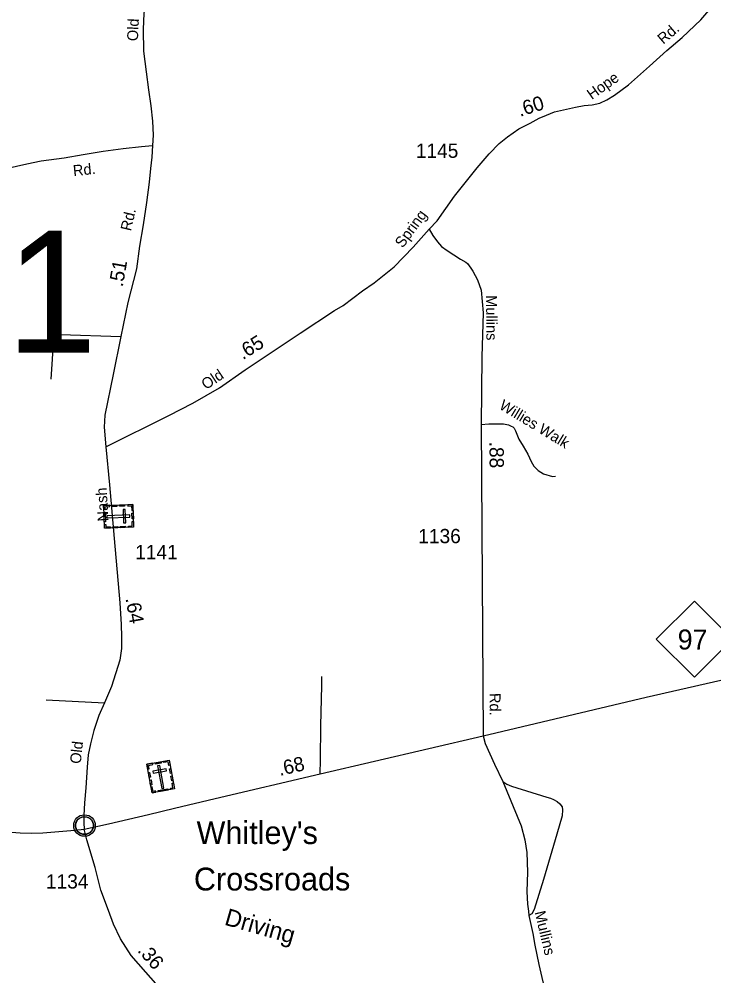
# Model space of a CAD drawing. Extents: x 2220236 to 2384410, y 720751 to 894131.
# Drawn here: x 2249679 to 2255753, y 766439 to 774813 of the extents above; entities that cross this region are included whole.
import ezdxf

# ---------------------------------------------------------------- set-up
doc = ezdxf.new("R2010")
doc.units = 0
doc.layers.add('Default', color=7, linetype='Continuous')

msp = doc.modelspace()

# ---------------------------------------------------------------- linework, layer by layer
at = {"layer": 'Default'}
msp.add_line((2249914.9, 768855.1), (2250426.3, 768828.7), dxfattribs=at)
for points in [[(2252290.3, 777623.5), (2252187.8, 777438.5), (2252085.3, 777242.3), (2251849.1, 776795.2), (2251710.9, 776529.9), (2251448, 776033.8), (2251392.3, 775951.3), (2251316.6, 775855.4), (2251158.3, 775661.4), (2251053.6, 775541), (2250986.8, 775447.4), (2250899.1, 775299.6), (2250856.5, 775184.3), (2250788.5, 774959.1), (2250769.2, 774863.9), (2250761.7, 774722.8), (2250766.2, 774531), (2250788.5, 774352.6), (2250808.5, 774194.3), (2250830.8, 774053.9), (2250844.2, 773920.1), (2250850.9, 773797.5), (2250845.5, 773705.6)], [(2253265, 772975.5), (2253333.2, 773046.7), (2253484, 773264.4), (2253684.2, 773511.1), (2253787.2, 773633), (2253875.7, 773724.5), (2253949.7, 773781.1), (2254046.8, 773853.7), (2254148.4, 773903), (2254225.3, 773945.1), (2254290.5, 773971.2), (2254359.1, 774001.2), (2254542.7, 774042.6), (2254618.4, 774055.4), (2254688, 774062.7), (2254757.6, 774078.6), (2254818.5, 774106.2), (2254885.3, 774146.9), (2255007.1, 774238.3), (2255189.9, 774402.3), (2255342.2, 774538.8), (2255475.9, 774650.5), (2255640.3, 774805.1), (2255710.7, 774887.4)], [(2247300.4, 773456), (2247377.2, 773386.3), (2247502, 773297.8), (2247596.3, 773248.4), (2247713.8, 773210.7), (2247824, 773184.5), (2247986.7, 773173.6), (2248156.7, 773167), (2248298.3, 773171.5), (2248369.4, 773175.8), (2248508.7, 773202), (2248595.7, 773226.6), (2248935.1, 773373.2), (2249150.2, 773418.9), (2249332.6, 773460.3), (2249566.1, 773503.9), (2249744.5, 773546), (2249870.7, 773573.5), (2250072.3, 773599.7), (2250239.2, 773628.7), (2250414.7, 773656.3), (2250588.7, 773679.5), (2250749.3, 773697.9), (2250845.5, 773705.6)], [(2250845.5, 773705.6), (2250839.7, 773605.5), (2250828.1, 773503.9), (2250815, 773386.3), (2250791.8, 773206.3), (2250762.8, 773013.3), (2250732.3, 772824.6), (2250704.1, 772625.9), (2250629.4, 772332.5), (2250567, 772035), (2250501.7, 771701.1), (2250429.2, 771347), (2250421.9, 771241), (2250437.9, 771068.3)], [(2250437.9, 771068.3), (2250987.7, 771344.1), (2251198, 771451.5), (2251430.1, 771586.5), (2251656.4, 771741.8), (2252136.5, 772064), (2252435.3, 772261.4), (2252510.7, 772306.4), (2252681.9, 772435.6), (2252782, 772505.3), (2252957.5, 772644.6), (2253124.3, 772815.9), (2253265, 772975.5)], [(2253265, 772975.5), (2253295.5, 772917.5), (2253336.1, 772863.8), (2253372.3, 772821.7), (2253421.7, 772788.3), (2253537.9, 772713), (2253584.1, 772685.5), (2253598.2, 772673.6), (2253628.6, 772633.8), (2253646.8, 772606), (2253687.1, 772529.9), (2253719, 772439.9), (2253736.4, 772241.1), (2253723.4, 771856.5), (2253717.6, 771265.7), (2253734.9, 768539)], [(2249960, 771662.2), (2249983.3, 772014.3), (2249981.1, 772024.3), (2249987.1, 772036.4), (2249994.9, 772046.4), (2250038.8, 772052.7), (2250567, 772035)], [(2253717.6, 771265.7), (2253785.6, 771271.7), (2253913.4, 771271.5), (2253958.4, 771262.8), (2253980.1, 771251.2), (2253994.6, 771243.9), (2254006.9, 771232.3), (2254019, 771208.3), (2254046.8, 771136.5), (2254084.6, 771075.6), (2254126.6, 771005.9), (2254155.6, 770940.6), (2254180.3, 770899.9), (2254218, 770862.2), (2254263, 770833.8), (2254341.1, 770810.4), (2254369.2, 770812.6)], [(2250437.9, 771068.3), (2250468.4, 770737.4), (2250510.4, 770267.1), (2250558.3, 769702.5), (2250571.3, 769515.2), (2250574.2, 769404.9), (2250574.2, 769304.8), (2250559.7, 769201.7), (2250485.8, 768970.9), (2250426.3, 768828.7), (2250375.5, 768716.9), (2250330.6, 768586.3), (2250303, 768470.2), (2250282.7, 768372.9), (2250274, 768264.1), (2250262.4, 768085.6), (2250250.8, 767953.5), (2250245, 767841.7), (2250243.5, 767779.3), (2250246.4, 767722.7)], [(2253734.9, 768539), (2255161.1, 768878.8), (2256633.9, 769214.7), (2257369.4, 769370.1), (2257914.6, 769486.6), (2258319.4, 769575.3), (2258459.9, 769593.4)], [(2252310.5, 768205.9), (2252314.9, 768330.8), (2252317.8, 768626.9), (2252325.1, 768981.1), (2252325.1, 769059.5)], [(2250246.4, 767722.7), (2250459.7, 767769.1), (2250810.7, 767850.4), (2251037, 767907), (2251392.4, 767991.2), (2252310.5, 768205.9), (2253734.9, 768539)], [(2253734.9, 768539), (2253754.3, 768471.1), (2253835.8, 768290.5), (2253909.1, 768139.9), (2254068.6, 767750.7), (2254101.6, 767628.4), (2254119.1, 767517.7), (2254123, 767344.9), (2254119.1, 767177.9), (2254123, 767067.2), (2254132.7, 767005.1), (2254136.5, 766966.2), (2254169.5, 766809), (2254187, 766706.1), (2254223.9, 766539.1), (2254287.9, 766261.4), (2254320.9, 766094.4), (2254309.2, 765814.8), (2254291.8, 765492.5), (2254313.1, 764991.5), (2254322.8, 764403.2)], [(2253909.1, 768139.9), (2253943.2, 768116.2), (2253985.2, 768098.6), (2254291.8, 768003.1), (2254324.8, 767995.3), (2254350, 767981.8), (2254383, 767964.3), (2254406.3, 767942.9), (2254427.6, 767917.7), (2254429.6, 767890.5), (2254425.7, 767840), (2254381, 767678.8), (2254262.7, 767282.7), (2254183.1, 767018.7), (2254161.8, 766981.8), (2254136.5, 766966.2)], [(2249069.9, 767801), (2249296.1, 767758.5), (2249610.6, 767697.2), (2249688.6, 767689.8), (2249782.6, 767688.5), (2249884.4, 767691.4), (2250165.2, 767714), (2250246.4, 767722.7)], [(2251150.1, 766066.6), (2251054.4, 766168.2), (2250957.2, 766274.1), (2250658.9, 766618.2), (2250565.7, 766761.4), (2250503.2, 766891), (2250459.7, 767010), (2250394.3, 767189.9), (2250343.6, 767387.4), (2250270.8, 767630.5), (2250246.4, 767722.7)]]:
    msp.add_lwpolyline(points, dxfattribs=at)
for points in [[(2250673, 770563.9), (2250679.6, 770365), (2250425.1, 770356.5), (2250418.5, 770555.5)], [(2250419.6, 770522.4), (2250431.1, 770522.8), (2250430.4, 770544.8), (2250470.8, 770546.1), (2250470.4, 770557.3), (2250418.5, 770555.6)], [(2250488.4, 770557.9), (2250531.7, 770559.3), (2250532.1, 770547.9), (2250488.8, 770546.5)], [(2250555.6, 770560.1), (2250598.9, 770561.5), (2250599.2, 770550.1), (2250556, 770548.7)], [(2250606.3, 770520.9), (2250587.7, 770520.3), (2250591.6, 770402.6), (2250610.2, 770403.2)], [(2250629.7, 770562.5), (2250630.1, 770551.2), (2250662.2, 770552.2), (2250663.6, 770511.7), (2250674.7, 770512.1), (2250673, 770563.9)], [(2250431.9, 770498.5), (2250434.7, 770413.6), (2250423.3, 770413.3), (2250420.5, 770498.1)], [(2250647.3, 770454), (2250646.7, 770472.7), (2250444, 770465.9), (2250444.6, 770447.3)], [(2250636.2, 770363.4), (2250635.9, 770374.8), (2250668, 770375.9), (2250666.7, 770416.4), (2250677.8, 770416.8), (2250679.5, 770364.9)], [(2250675.4, 770489.9), (2250677.1, 770438.1), (2250665.8, 770437.7), (2250664, 770489.5)], [(2250424, 770389.6), (2250435.5, 770390), (2250436.2, 770368), (2250476.6, 770369.4), (2250477, 770358.2), (2250425.1, 770356.5)], [(2250496.9, 770370.3), (2250540.2, 770371.7), (2250540.6, 770360.3), (2250497.3, 770358.9)], [(2250562.8, 770372.4), (2250606.1, 770373.9), (2250606.5, 770362.5), (2250563.2, 770361.1)], [(2255250.1, 769384.8), (2255583.1, 769717.8), (2255916.1, 769384.8), (2255583.1, 769051.8)], [(2250795.1, 768290.2), (2250991, 768326), (2251036.7, 768075.5), (2250840.9, 768039.8)], [(2250998.8, 768283.4), (2250987.7, 768281.3), (2250981.9, 768313), (2250942, 768305.7), (2250940, 768316.6), (2250991.1, 768326)], [(2250802.9, 768247.6), (2250814.1, 768249.7), (2250808.3, 768281.3), (2250848.2, 768288.6), (2250846.2, 768299.6), (2250795.1, 768290.2)], [(2250847.5, 768230.6), (2250850.9, 768212.3), (2250966.7, 768233.4), (2250963.3, 768251.8)], [(2250868, 768303.5), (2250919, 768312.8), (2250921, 768301.6), (2250870.1, 768292.3)], [(2250907.7, 768281), (2250889.3, 768277.6), (2250925.7, 768078.2), (2250944.1, 768081.5)], [(2251000.7, 768209.4), (2250993, 768252), (2251004.2, 768254.1), (2251011.9, 768211.5)], [(2250816.2, 768174.7), (2250808.4, 768217.3), (2250819.6, 768219.3), (2250827.4, 768176.7)], [(2251012.6, 768144.6), (2251004.8, 768187.2), (2251016, 768189.2), (2251023.8, 768146.6)], [(2250828.3, 768108.6), (2250820.5, 768151.2), (2250831.7, 768153.2), (2250839.5, 768110.6)], [(2250873.4, 768045.7), (2250871.3, 768057), (2250849.7, 768053.1), (2250842.4, 768092.9), (2250831.5, 768090.9), (2250840.8, 768039.8)], [(2250895.3, 768061.4), (2250978.8, 768076.6), (2250980.9, 768065.4), (2250897.4, 768050.2)], [(2251004.1, 768069.6), (2251002.1, 768080.9), (2251023.7, 768084.8), (2251016.4, 768124.6), (2251027.4, 768126.6), (2251036.7, 768075.5)], [(2250172.4, 767766.6), (2250173.3, 767772.2), (2250175.1, 767778.8), (2250178, 767786), (2250181, 767791.7), (2250184.3, 767797.4), (2250188.1, 767802.6), (2250192, 767806.9), (2250196.6, 767811.5), (2250202.1, 767816.1), (2250207.6, 767819.8), (2250212.5, 767822.6), (2250217.5, 767825.1), (2250223, 767827.4), (2250228.6, 767829.2), (2250232.9, 767830.4), (2250237.8, 767831.1), (2250241.9, 767831.8), (2250248.3, 767832.1), (2250252.7, 767832), (2250258.4, 767831.7), (2250263.3, 767831), (2250268.2, 767830), (2250273.2, 767828.6), (2250278.4, 767826.7), (2250285, 767823.7), (2250291.3, 767820.2), (2250296.3, 767816.7), (2250301.5, 767812.7), (2250304.8, 767809.5), (2250308.9, 767805.2), (2250312.8, 767800.5), (2250315.9, 767795.9), (2250319, 767790.9), (2250321.5, 767785.7), (2250323.5, 767780.7), (2250325.1, 767775.7), (2250326.3, 767771.1), (2250327.4, 767765), (2250328.1, 767760.3), (2250328.3, 767754.3), (2250328.1, 767748.6), (2250327.6, 767742.9), (2250326.6, 767737.4), (2250325, 767731.2), (2250323.1, 767725.4), (2250320.8, 767720.3), (2250317.6, 767714.3), (2250314.4, 767709), (2250310.9, 767704.3), (2250306.7, 767699.6), (2250301.4, 767694.6), (2250296.4, 767690.5), (2250291.4, 767687), (2250287, 767684.5), (2250280.2, 767681.3), (2250273.1, 767678.6), (2250267.1, 767677.1), (2250260.5, 767675.8), (2250256.1, 767675.3), (2250251.6, 767675.1), (2250246, 767675.1), (2250241.8, 767675.5), (2250236.1, 767676.2), (2250230.2, 767677.5), (2250225.6, 767678.8), (2250220.4, 767680.7), (2250215.8, 767682.7), (2250211.9, 767684.9), (2250205.1, 767689), (2250199.5, 767693.3), (2250194.6, 767697.8), (2250190.2, 767702.6), (2250187, 767706.6), (2250184, 767710.8), (2250179.9, 767717.9), (2250178.2, 767721.4), (2250176.5, 767725.4), (2250173.9, 767733.6), (2250172.4, 767740.7), (2250171.7, 767745.8), (2250171.3, 767752.2), (2250171.3, 767756.8), (2250171.8, 767763.3)]]:
    msp.add_lwpolyline(points, close=True, dxfattribs=at)
for centre, radius in [((2250250, 767754.2), 94.3), ((2250249.7, 767754.5), 76.7)]:
    msp.add_circle(centre, radius, dxfattribs=at)

# ---------------------------------------------------------------- texts
for s, height, rotation, p in [('Old', 95, 87.32592, (2250716.7, 774618.6)), ('Rd.', 95, 40.57759, (2255310.7, 774588.1)), ('Hope', 95, 35.4105, (2254686, 774103.9)), ('.60', 125, 17.41614, (2254058.3, 773957.4)), ('Rd.', 95, 5.6293, (2250153.9, 773438.9)), ('Rd.', 95, 76.75065, (2250655.7, 772952.8)), ('Spring', 95, 53.59115, (2253032.5, 772803.5)), ('.51', 125, 79.83101, (2250583.5, 772463.5)), ('Mullins', 95, 270.42356, (2253761, 772395.9)), ('.65', 125, 31.84668, (2251634.6, 771827)), ('Old', 95, 33.58595, (2251312.3, 771565.9)), ('Willies Walk', 95, 328.75552, (2253868.1, 771406.7)), ('.88', 125, 270.42356, (2253791, 771114)), ('Nash', 95, 93.4072, (2250460.7, 770418.8)), ('.64', 125, 279.9855, (2250608.3, 769741.9)), ('Rd.', 95, 270.42356, (2253792.8, 768914.3)), ('Old', 95, 83.86656, (2250216.8, 768291)), ('.68', 125, 13.16259, (2251958.1, 768187.7)), ('Driving', 150, 344.22715, (2251466.1, 766887.5)), ('Mullins', 95, 283.42419, (2254185.3, 766995.7)), ('.36', 125, 310.92705, (2250707.8, 766657.2))]:
    msp.add_text(s, height=height, rotation=rotation, dxfattribs=at).set_placement(p)
for s, height, p in [('1145', 125, (2253147.2, 773598.5)), ('31', 1066.27, (2248771.7, 771893.5)), ('1136', 125, (2253168.7, 770225.8)), ('1141', 125, (2250693, 770085.3)), ('97', 175, (2255437.2, 769295.1)), ("Whitley's", 200, (2251229.8, 767592.4)), ('1134', 125, (2249912.9, 767203.1)), ('Crossroads', 200, (2251206.8, 767186))]:
    msp.add_text(s, height=height, dxfattribs=at).set_placement(p)

doc.saveas('drawing.dxf')
